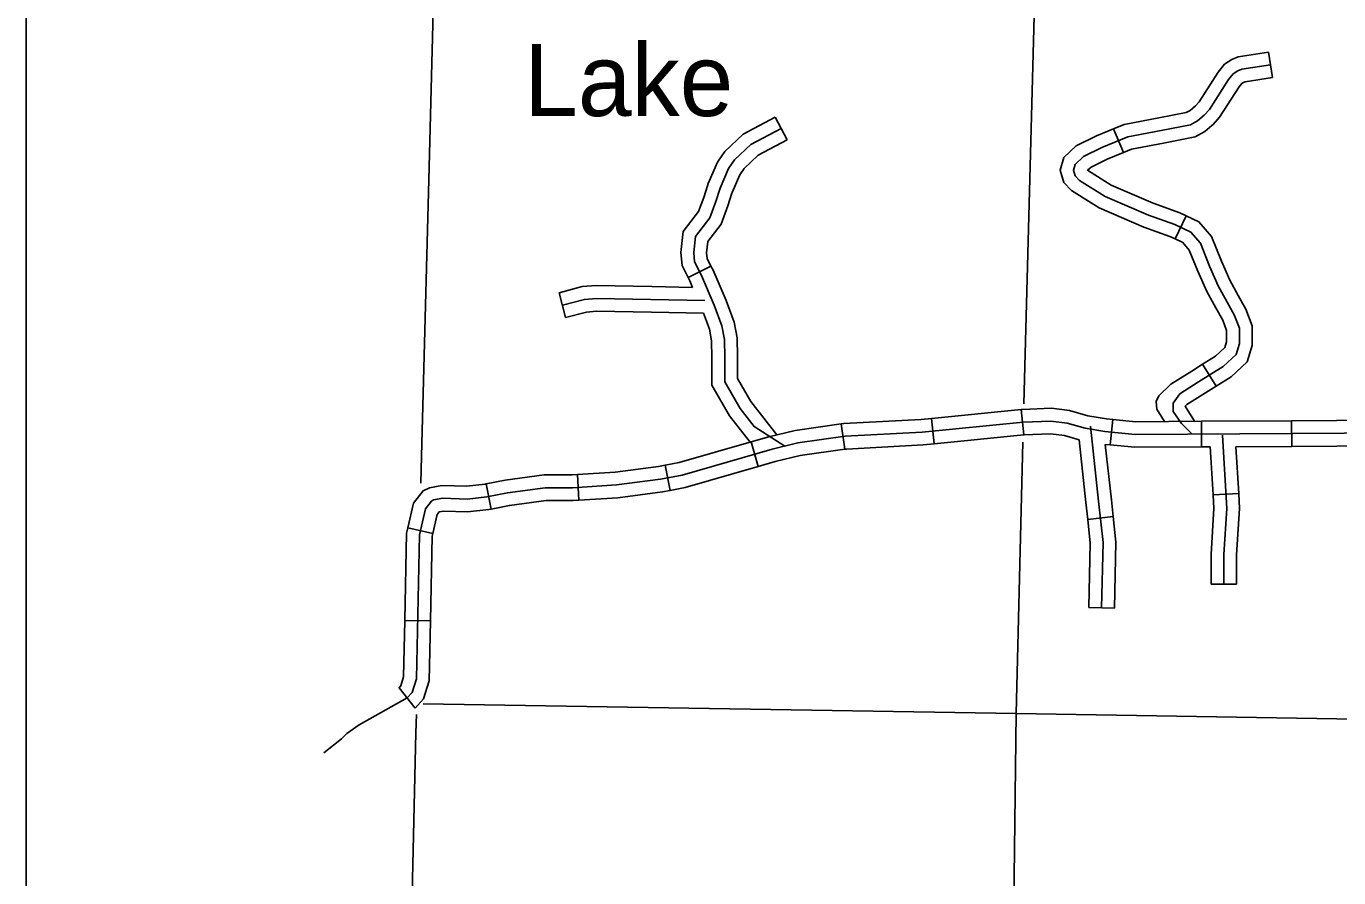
# Model space of a CAD drawing. Extents: x 1370567 to 1373900, y 377514 to 379648.
# Drawn here: x 1371518.1 to 1371737.8, y 378032.3 to 378174.9 of the extents above; entities that cross this region are included whole.
import ezdxf

# ---------------------------------------------------------------- set-up
doc = ezdxf.new("R2010")
doc.units = 0
doc.layers.add('Default', color=7, linetype='Continuous')
doc.layers.add('Survey Symbols', color=7, linetype='Continuous')

msp = doc.modelspace()

# ---------------------------------------------------------------- linework, layer by layer
at = {"layer": 'Default'}
for p, q in [((1371726.06, 378170.56), (1371726.73, 378166.32)), ((1371643.5, 378159.66), (1371645.5, 378155.87)), ((1371700.13, 378157.73), (1371701.76, 378153.77)), ((1371710.45, 378139.27), (1371712.28, 378143.14)), ((1371628.9, 378132.82), (1371632.73, 378134.73)), ((1371608.41, 378126.1), (1371607.3, 378130.24)), ((1371715.01, 378118.28), (1371717.27, 378114.64)), ((1371685.09, 378106.45), (1371684.67, 378110.71)), ((1371655.11, 378104.05), (1371654.51, 378108.3)), ((1371670.08, 378104.96), (1371669.65, 378109.22)), ((1371699.56, 378104.8), (1371699.98, 378109.06)), ((1371714.85, 378104.46), (1371714.82, 378108.74)), ((1371729.93, 378104.55), (1371729.91, 378108.84)), ((1371640.63, 378101.17), (1371639.45, 378105.29)), ((1371625.9, 378097.18), (1371625.09, 378101.39)), ((1371610.64, 378095.53), (1371610.37, 378099.81)), ((1371595.96, 378094.06), (1371595.11, 378098.26)), ((1371721.07, 378096.67), (1371716.79, 378096.41)), ((1371700.05, 378092.79), (1371695.79, 378092.33)), ((1371586.17, 378089.95), (1371582, 378090.92)), ((1371720.72, 378081.47), (1371716.43, 378081.47)), ((1371700.26, 378077.45), (1371695.97, 378077.55)), ((1371585.77, 378075.33), (1371581.49, 378075.42))]:
    msp.add_line(p, q, dxfattribs=at)
for points in [[(1371587.37, 378219.81), (1371586.63, 378192.56), (1371585.52, 378149.18), (1371584.28, 378102.88)], [(1371687.94, 378218.81), (1371687.76, 378212.21), (1371685.09, 378111.64)], [(1371726.06, 378170.56), (1371720.96, 378169.75), (1371719.9, 378169.3), (1371718.69, 378168.54), (1371717.63, 378167.22), (1371714.44, 378162.25), (1371713.81, 378161.54), (1371713.85, 378161.57)], [(1371726.4, 378168.44), (1371721.56, 378167.68), (1371720.9, 378167.39), (1371720.14, 378166.92), (1371719.38, 378165.97), (1371716.15, 378160.94), (1371715.3, 378159.99), (1371714.16, 378159.04), (1371713.02, 378158.38), (1371708.09, 378157.43), (1371702.5, 378156.39), (1371698.13, 378154.58), (1371695.1, 378153.07), (1371693.68, 378151.74), (1371693.39, 378150.79), (1371693.68, 378149.84), (1371694.44, 378149.08), (1371698.7, 378146.38), (1371705.96, 378143.24), (1371710.37, 378141.68), (1371713.07, 378140.4), (1371714.64, 378138.55), (1371716.2, 378134.7), (1371717.62, 378131.43), (1371720.33, 378126.59), (1371721.18, 378124.31), (1371721.18, 378121.75), (1371720.61, 378119.9), (1371718.48, 378117.91), (1371714.35, 378115.35), (1371711.22, 378113.35), (1371710.08, 378111.79), (1371710.08, 378110.36), (1371711.49, 378108.37), (1371713.29, 378106.59)], [(1371726.73, 378166.32), (1371722.16, 378165.6), (1371721.89, 378165.49), (1371721.58, 378165.3), (1371721.12, 378164.72), (1371717.86, 378159.64), (1371716.79, 378158.45), (1371716.59, 378158.28)], [(1371713.85, 378161.57), (1371712.93, 378160.8), (1371712.26, 378160.42), (1371707.69, 378159.54), (1371701.88, 378158.45), (1371700.13, 378157.73)], [(1371643.5, 378159.66), (1371638.12, 378156.82), (1371635.05, 378153.9), (1371633.8, 378152.12), (1371632.25, 378148.55), (1371632.14, 378148.19)], [(1371644.5, 378157.76), (1371639.38, 378155.06), (1371636.68, 378152.5), (1371635.68, 378151.07), (1371634.26, 378147.8), (1371633.55, 378145.52), (1371632.55, 378142.82), (1371630.14, 378139.69), (1371629.85, 378136.98), (1371629.99, 378135.42), (1371631.13, 378133.14), (1371633.27, 378128.16), (1371634.55, 378124.74), (1371634.97, 378122.46), (1371635.04, 378119.4), (1371635.04, 378115.35), (1371637.6, 378110.86), (1371639.95, 378107.87), (1371645.09, 378104.59)], [(1371700.13, 378157.73), (1371697.24, 378156.54), (1371693.86, 378154.84), (1371691.79, 378152.91), (1371691.16, 378150.79), (1371691.78, 378148.71), (1371693.09, 378147.4), (1371696.37, 378145.32)], [(1371716.59, 378158.28), (1371715.4, 378157.28), (1371713.79, 378156.34), (1371708.49, 378155.33), (1371703.11, 378154.32), (1371701.76, 378153.77)], [(1371645.5, 378155.87), (1371640.64, 378153.3), (1371638.31, 378151.09), (1371637.56, 378150.02), (1371636.27, 378147.05), (1371636.23, 378146.91)], [(1371701.76, 378153.77), (1371699.02, 378152.63), (1371696.34, 378151.29), (1371695.78, 378150.77), (1371695.78, 378150.76), (1371698.67, 378148.94)], [(1371632.14, 378148.19), (1371631.52, 378146.21), (1371630.66, 378143.87), (1371628.07, 378140.51), (1371627.7, 378137), (1371627.9, 378134.82), (1371628.9, 378132.82)], [(1371698.67, 378148.94), (1371699.71, 378148.28), (1371706.74, 378145.24), (1371711.19, 378143.66), (1371712.28, 378143.14)], [(1371636.23, 378146.91), (1371635.58, 378144.83), (1371634.45, 378141.77), (1371632.2, 378138.86), (1371632, 378136.97), (1371632.09, 378136.01), (1371632.73, 378134.73)], [(1371696.37, 378145.32), (1371697.7, 378144.48), (1371705.17, 378141.25), (1371709.55, 378139.7), (1371710.45, 378139.27)], [(1371712.28, 378143.14), (1371714.41, 378142.14), (1371716.49, 378139.67), (1371718.18, 378135.54), (1371719.55, 378132.38), (1371720.98, 378129.81)], [(1371710.45, 378139.27), (1371711.73, 378138.66), (1371712.78, 378137.42), (1371714.23, 378133.87), (1371715.7, 378130.48), (1371717.24, 378127.72)], [(1371632.73, 378134.73), (1371633.08, 378134.04), (1371635.25, 378128.95), (1371636.62, 378125.32), (1371637.11, 378122.69), (1371637.18, 378119.53)], [(1371628.9, 378132.82), (1371629.19, 378132.24), (1371629.65, 378131.17)], [(1371607.3, 378130.24), (1371611.2, 378131.29), (1371613.49, 378131.45), (1371622.84, 378131.29)], [(1371622.84, 378131.29), (1371629.65, 378131.17)], [(1371607.86, 378128.17), (1371611.55, 378129.16), (1371613.55, 378129.31), (1371631.72, 378128.99)], [(1371717.24, 378127.72), (1371718.38, 378125.69), (1371719.04, 378123.92), (1371719.04, 378122.07), (1371718.73, 378121.08), (1371717.17, 378119.62), (1371715.01, 378118.28)], [(1371720.98, 378129.81), (1371722.28, 378127.49), (1371723.32, 378124.7), (1371723.32, 378121.43), (1371722.49, 378118.72), (1371719.79, 378116.2), (1371717.27, 378114.64)], [(1371608.41, 378126.1), (1371611.91, 378127.04), (1371613.6, 378127.16), (1371622.77, 378127)], [(1371622.77, 378127), (1371631.47, 378126.85)], [(1371631.47, 378126.85), (1371632.47, 378124.16), (1371632.83, 378122.24), (1371632.9, 378119.43)], [(1371632.9, 378119.43), (1371632.9, 378119.38), (1371632.9, 378114.78), (1371635.82, 378109.66), (1371639.29, 378105.24)], [(1371637.18, 378119.53), (1371637.19, 378119.43), (1371637.19, 378115.91), (1371639.39, 378112.06), (1371643.78, 378106.47)], [(1371715.01, 378118.28), (1371713.21, 378117.16), (1371709.73, 378114.94), (1371707.68, 378113.01), (1371707.27, 378112.06), (1371707.34, 378110.79), (1371708.63, 378108.71)], [(1371717.27, 378114.64), (1371715.49, 378113.53), (1371712.37, 378111.55), (1371712.08, 378111.27), (1371713.65, 378108.74)], [(1371669.65, 378109.22), (1371684.67, 378110.71)], [(1371684.67, 378110.71), (1371684.86, 378110.73), (1371689.73, 378110.94), (1371692.76, 378110.54), (1371695.81, 378109.68), (1371698.95, 378109.17), (1371699.98, 378109.06)], [(1371567.91, 378053.22), (1371570.9, 378055.56), (1371571.77, 378056.46), (1371573.86, 378057.92), (1371581.89, 378062.44), (1371582.73, 378063.36), (1371583.43, 378065.63), (1371583.93, 378089.76), (1371584.93, 378094.08), (1371585.94, 378095.39), (1371586.31, 378095.57), (1371587.87, 378095.85), (1371591.9, 378095.72), (1371595.24, 378096.1), (1371598.66, 378096.79), (1371604.98, 378097.61), (1371609.58, 378097.61), (1371616.92, 378098.09), (1371624.27, 378099.05), (1371627.89, 378099.74), (1371642.95, 378104.07), (1371647.25, 378105.11), (1371655.2, 378106.23), (1371668.1, 378106.92), (1371685.01, 378108.59), (1371689.64, 378108.79), (1371692.33, 378108.44), (1371695.34, 378107.58), (1371698.67, 378107.04), (1371703.76, 378106.53), (1371808.75, 378107.18)], [(1371639.45, 378105.29), (1371642.4, 378106.14), (1371646.84, 378107.22), (1371654.51, 378108.3)], [(1371654.51, 378108.3), (1371654.99, 378108.36), (1371667.94, 378109.05), (1371669.65, 378109.22)], [(1371698.12, 378077.5), (1371698.36, 378088.43), (1371697.62, 378095.39), (1371696.24, 378107.95)], [(1371699.98, 378109.06), (1371703.86, 378108.68), (1371714.82, 378108.74)], [(1371714.82, 378108.74), (1371729.91, 378108.84)], [(1371729.91, 378108.84), (1371744.99, 378108.93)], [(1371670.08, 378104.96), (1371685.09, 378106.45)], [(1371685.09, 378106.45), (1371685.16, 378106.45), (1371689.54, 378106.64), (1371691.89, 378106.34), (1371694.34, 378105.64)], [(1371718.57, 378081.47), (1371718.57, 378086.44), (1371719.07, 378094.15), (1371718.33, 378106.44)], [(1371625.09, 378101.39), (1371627.39, 378101.83), (1371639.45, 378105.29)], [(1371640.63, 378101.17), (1371643.5, 378101.99), (1371647.65, 378103.01), (1371655.11, 378104.05)], [(1371655.11, 378104.05), (1371655.4, 378104.09), (1371668.26, 378104.78), (1371670.08, 378104.96)], [(1371684.93, 378105.24), (1371683.82, 378059.8), (1371683.36, 378023.42)], [(1371695.79, 378092.33), (1371695.49, 378095.16), (1371694.34, 378105.64)], [(1371700.05, 378092.79), (1371699.75, 378095.62), (1371698.73, 378104.88)], [(1371698.73, 378104.88), (1371699.56, 378104.8)], [(1371699.56, 378104.8), (1371703.66, 378104.39), (1371714.85, 378104.46)], [(1371714.85, 378104.46), (1371716.3, 378104.47)], [(1371716.79, 378096.41), (1371716.3, 378104.47)], [(1371720.59, 378104.49), (1371729.93, 378104.55)], [(1371721.07, 378096.67), (1371720.59, 378104.49)], [(1371729.93, 378104.55), (1371745.02, 378104.64)], [(1371584.28, 378102.88), (1371584.16, 378098.38)], [(1371610.37, 378099.81), (1371616.71, 378100.22), (1371623.93, 378101.16), (1371625.09, 378101.39)], [(1371595.11, 378098.26), (1371598.3, 378098.9), (1371604.84, 378099.76), (1371609.51, 378099.76), (1371610.37, 378099.81)], [(1371625.9, 378097.18), (1371628.39, 378097.65), (1371640.63, 378101.17)], [(1371582, 378090.92), (1371582.95, 378095.02), (1371584.55, 378097.1), (1371585.64, 378097.62), (1371587.71, 378098), (1371591.82, 378097.87), (1371594.91, 378098.22), (1371595.11, 378098.26)], [(1371610.64, 378095.53), (1371617.13, 378095.95), (1371624.61, 378096.93), (1371625.9, 378097.18)], [(1371595.96, 378094.06), (1371599.01, 378094.67), (1371605.12, 378095.47), (1371609.65, 378095.47), (1371610.64, 378095.53)], [(1371716.43, 378081.47), (1371716.43, 378086.51), (1371716.92, 378094.15), (1371716.79, 378096.41)], [(1371720.72, 378081.47), (1371720.72, 378086.38), (1371721.22, 378094.14), (1371721.07, 378096.67)], [(1371586.17, 378089.95), (1371586.92, 378093.15), (1371587.23, 378093.56), (1371588.03, 378093.7), (1371591.99, 378093.58), (1371595.57, 378093.98), (1371595.96, 378094.06)], [(1371700.26, 378077.45), (1371700.51, 378088.52), (1371700.05, 378092.79)], [(1371581.49, 378075.42), (1371581.79, 378090.02), (1371582, 378090.92)], [(1371695.97, 378077.55), (1371696.22, 378088.34), (1371695.79, 378092.33)], [(1371585.77, 378075.33), (1371586.07, 378089.49), (1371586.17, 378089.95)], [(1371583.24, 378060.74), (1371580.53, 378064.13), (1371580.82, 378064.45), (1371581.29, 378065.98), (1371581.49, 378075.42)], [(1371583.24, 378060.74), (1371584.63, 378062.28), (1371585.56, 378065.29), (1371585.77, 378075.33)], [(1371583.43, 378059.63), (1371583.36, 378056.58)], [(1371584.55, 378061.45), (1371683.82, 378059.8), (1371811.23, 378057.69)], [(1371583.36, 378056.58), (1371582.29, 378010.07)]]:
    msp.add_lwpolyline(points, dxfattribs=at)
at = {"layer": 'Survey Symbols'}
msp.add_lwpolyline([(1371518.13, 378743.2), (1373025.55, 378743.2), (1373025.55, 377817.56), (1371518.13, 377817.56)], close=True, dxfattribs=at)
msp.add_lwpolyline([(1371518.13, 378743.2), (1373025.55, 378743.2), (1373025.55, 377817.56), (1371518.13, 377817.56)], close=True, dxfattribs=at)
msp.add_lwpolyline([(1371518.13, 378743.2), (1373025.55, 378743.2), (1373025.55, 377817.56), (1371518.13, 377817.56)], close=True, dxfattribs=at)

# ---------------------------------------------------------------- texts
at = {"layer": 'Default'}
msp.add_text('Lake', height=12.069, dxfattribs=at).set_placement((1371601.48, 378159.85))

doc.saveas('drawing.dxf')
